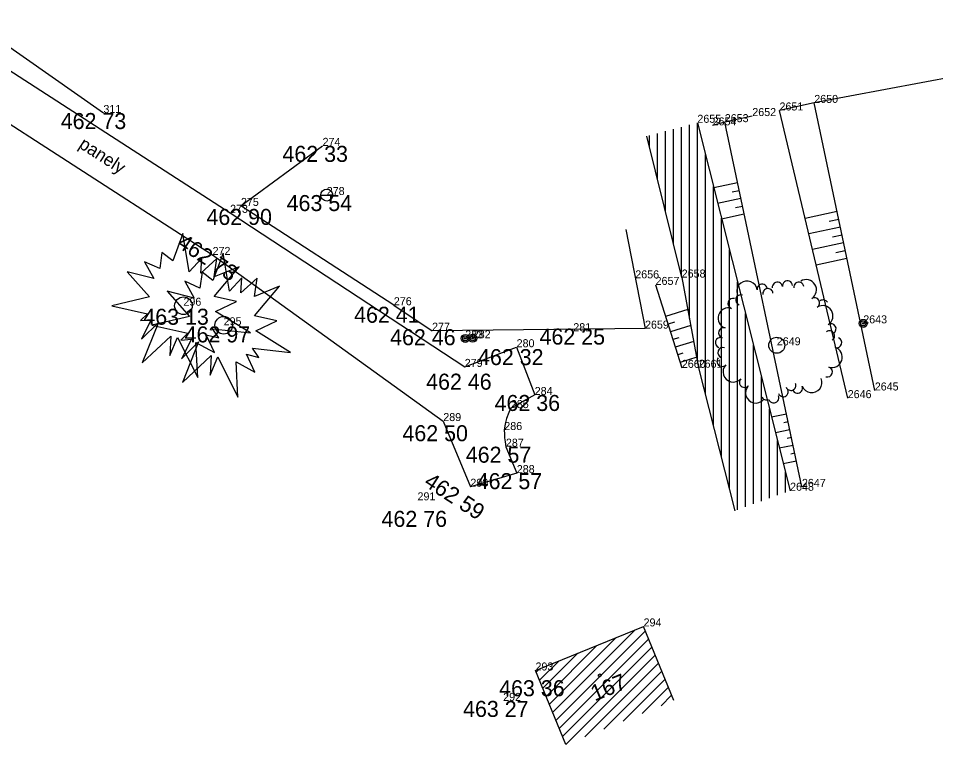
# Model space of a CAD drawing. Extents: x -559180 to -551373, y -1076947 to -1072071.
# Drawn here: x -553687 to -553629.7, y -1075512.9 to -1075467.6 of the extents above; entities that cross this region are included whole.
import ezdxf

# ---------------------------------------------------------------- set-up
doc = ezdxf.new("R2010")
doc.units = 0
for name, color, linetype in [('12_PLOTY', 7, 'Continuous'), ('14_BUDOVY', 7, 'Continuous'), ('17_KOMUNIKACE', 7, 'Continuous'), ('1_VODA_ZN', 7, 'Continuous'), ('20_EL_ZN', 7, 'Continuous'), ('26_SRAFY', 7, 'Continuous'), ('27_HRANA_PATA', 7, 'Continuous'), ('28_VODA', 7, 'Continuous'), ('32', 7, 'Continuous'), ('34_ZELEN', 7, 'Continuous'), ('3_BODY', 7, 'Continuous'), ('47_ZN_STAV_OBJ$', 7, 'Continuous'), ('52_POPIS_UCELOVY', 7, 'Continuous'), ('54_C_POPISNA', 7, 'Continuous'), ('6_VYSKY', 7, 'Continuous')]:
    doc.layers.add(name, color=color, linetype=linetype)

# ---------------------------------------------------------------- blocks, each defined once
blk = doc.blocks.new('POINT_DISPLAY')
blk.add_line((0, 0), (0, 0))
blk = doc.blocks.new('ST')
at = {"layer": '1_VODA_ZN'}
blk.add_line((-0.375, 0), (0.375, 0), dxfattribs=at)
blk.add_circle((0, 0), 0.375, dxfattribs=at)
blk = doc.blocks.new('SLDP')
at = {"layer": '20_EL_ZN'}
for radius in [0.25, 0.158, 0.05]:
    blk.add_circle((0, 0), radius, dxfattribs=at)
blk = doc.blocks.new('STJV')
at = {"layer": '34_ZELEN'}
blk.add_lwpolyline([(-4.477, 0), (-2.236, -0.499), (-2.682, -0.926), (-2.012, -0.869), (-2.627, -2.092), (-1.566, -1.04), (-2.57, -3.572), (-0.785, -1.893), (-0.841, -3.117), (-0.366, -1.979), (0.889, -4.483), (0.777, -2.291), (1.949, -2.917), (1.419, -1.808), (2.2, -2.006), (1.808, -1.437), (4.179, -1.694), (2.004, -0.356), (3.314, 0.27), (1.921, 0.582), (3.483, 2.432), (1.921, 1.806), (2.087, 2.944), (1.083, 2.034), (1.14, 2.972), (0.359, 2.119), (-0.033, 4.509), (-0.673, 2.802), (-1.343, 3.314), (-1.483, 2.318), (-2.431, 2.745), (-1.845, 1.692), (-3.519, 2.119), (-2.123, 0.554), (-4.477, 0)], dxfattribs=at)
blk.add_circle((0, 0), 0.55, dxfattribs=at)
blk = doc.blocks.new('BZ')
at = {"layer": '47_ZN_STAV_OBJ$'}
blk.add_circle((0, 0), 0.0875, dxfattribs=at)
blk = doc.blocks.new('STLV')
at = {"layer": '34_ZELEN'}
blk.add_circle((0, 0), 0.5, dxfattribs=at)
for centre, radius, start, end in [((-1.866, 3.377), 0.64, 7.279, 187.2791), ((0.673, 3.701), 0.32, 7.279, 187.2791), ((1.839, 3.46), 0.64, 302.4264, 122.4264), ((-0.914, 3.498), 0.32, 7.279, 187.2791), ((-0.552, 3.222), 0.32, 97.2791, 188.0812), ((-0.556, 3.222), 0.32, 6.4769, 97.2791), ((0.038, 3.62), 0.32, 7.279, 187.2791), ((1.372, 3.62), 0.32, 7.279, 187.2791), ((-2.733, 2.607), 0.32, 72.1317, 252.1317), ((-2.248, 2.834), 0.32, 72.1317, 252.1317), ((2.354, 2.649), 0.32, 302.4264, 122.4264), ((-3.027, 1.693), 0.64, 72.1317, 252.1317), ((2.869, 1.839), 0.64, 302.4264, 122.4264), ((2.893, 2.511), 0.32, 32.4264, 123.2285), ((3.383, 1.029), 0.32, 302.4264, 122.4264), ((-3.322, 0.779), 0.32, 72.1317, 252.1317), ((3.287, 0.583), 0.32, 32.4264, 123.2285), ((3.285, 0.587), 0.32, 301.6242, 32.4264), ((-3.518, 0.17), 0.32, 72.1317, 252.1317), ((3.746, 0.168), 0.32, 252.1317, 72.1317), ((-3.366, -0.453), 0.32, 72.1317, 252.1317), ((3.452, -0.746), 0.64, 252.1317, 72.1317), ((-3.419, -1.001), 0.32, 136.9844, 316.9844), ((-2.717, -1.656), 0.64, 136.9844, 316.9844), ((3.157, -1.66), 0.32, 252.1317, 72.1317), ((-2.015, -2.311), 0.32, 136.9844, 316.9844), ((2.185, -2.318), 0.64, 201.8371, 21.8371), ((-1.313, -2.966), 0.64, 136.9844, 316.9844), ((0.402, -2.891), 0.32, 201.8371, 21.8371), ((0.877, -2.497), 0.32, 201.035, 291.8371), ((0.873, -2.499), 0.32, 291.8371, 22.6393), ((1.293, -2.675), 0.32, 201.8371, 21.8371), ((-0.639, -3.093), 0.32, 201.035, 291.8371), ((-0.192, -3.27), 0.32, 201.8371, 21.8371)]:
    blk.add_arc(centre, radius, start, end, dxfattribs=at)
blk.add_blockref('POINT_DISPLAY', (0, 0), dxfattribs=at)

msp = doc.modelspace()

# ---------------------------------------------------------------- linework, layer by layer
at = {"layer": '12_PLOTY'}
for p, q in [((-553681.67, -1075473.52), (-553690.11, -1075467.61)), ((-553624.38, -1075470.48), (-553637.27, -1075472.89)), ((-553637.27, -1075472.89), (-553639.44, -1075473.36)), ((-553641.14, -1075473.71), (-553642.86, -1075474.09)), ((-553642.86, -1075474.09), (-553643.62, -1075474.29)), ((-553673.08, -1075479.32), (-553667.98, -1075475.57)), ((-553663.53, -1075485.52), (-553673.08, -1075479.32)), ((-553649.044, -1075480.781), (-553647.84, -1075486.98)), ((-553663.53, -1075485.52), (-553661.14, -1075487.11)), ((-553647.84, -1075486.98), (-553661.14, -1075487.11)), ((-553655.85, -1075496), (-553658.75, -1075496.85))]:
    msp.add_line(p, q, dxfattribs=at)
at = {"layer": '14_BUDOVY'}
for p, q in [((-553654.68, -1075508.32), (-553647.93, -1075505.57)), ((-553646.044, -1075510.2), (-553647.93, -1075505.57)), ((-553652.794, -1075512.95), (-553654.68, -1075508.32))]:
    msp.add_line(p, q, dxfattribs=at)
at = {"layer": '17_KOMUNIKACE'}
for p, q in [((-553691.57, -1075468.24), (-553673.76, -1075479.75)), ((-553692.78, -1075470.82), (-553674.85, -1075482.38)), ((-553673.76, -1075479.75), (-553659.1, -1075489.37)), ((-553674.85, -1075482.38), (-553660.44, -1075492.75)), ((-553659.1, -1075489.37), (-553655.86, -1075488.14)), ((-553655.86, -1075488.14), (-553654.73, -1075491.12)), ((-553654.73, -1075491.12), (-553656.22, -1075491.94)), ((-553660.44, -1075492.75), (-553658.75, -1075496.85)), ((-553656.53, -1075494.35), (-553655.85, -1075496))]:
    msp.add_line(p, q, dxfattribs=at)
for points in [[(-553656.22, -1075491.94), (-553656.354, -1075492.223), (-553656.488, -1075492.594), (-553656.571, -1075492.926), (-553656.63, -1075493.31)], [(-553656.63, -1075493.31), (-553656.627, -1075493.554), (-553656.609, -1075493.795), (-553656.579, -1075494.056), (-553656.53, -1075494.35)]]:
    msp.add_lwpolyline(points, dxfattribs=at)
at = {"layer": '26_SRAFY'}
for p, q in [((-553643.549, -1075478.179), (-553642.061, -1075477.864)), ((-553643.305, -1075479.15), (-553641.854, -1075478.843)), ((-553642.398, -1075478.447), (-553641.958, -1075478.353)), ((-553642.18, -1075479.423), (-553641.75, -1075479.332)), ((-553643.06, -1075480.12), (-553641.647, -1075479.821)), ((-553637.847, -1075480.076), (-553635.845, -1075479.655)), ((-553637.616, -1075481.049), (-553635.639, -1075480.633)), ((-553636.339, -1075480.27), (-553635.742, -1075480.144)), ((-553636.126, -1075481.247), (-553635.536, -1075481.122)), ((-553637.385, -1075482.023), (-553635.433, -1075481.612)), ((-553635.912, -1075482.224), (-553635.33, -1075482.101)), ((-553637.154, -1075482.996), (-553635.227, -1075482.59)), ((-553645.172, -1075485.795), (-553646.552, -1075486.232)), ((-553646.005, -1075486.583), (-553646.402, -1075486.709)), ((-553644.986, -1075486.785), (-553646.251, -1075487.186)), ((-553645.738, -1075487.548), (-553646.1, -1075487.662)), ((-553644.799, -1075487.775), (-553645.949, -1075488.139)), ((-553645.47, -1075488.512), (-553645.798, -1075488.616)), ((-553644.613, -1075488.765), (-553645.647, -1075489.092)), ((-553639.942, -1075492.49), (-553639.007, -1075492.292)), ((-553639.178, -1075492.839), (-553638.903, -1075492.781)), ((-553639.697, -1075493.46), (-553638.8, -1075493.27)), ((-553638.96, -1075493.815), (-553638.696, -1075493.759)), ((-553639.453, -1075494.431), (-553638.593, -1075494.249)), ((-553638.742, -1075494.791), (-553638.489, -1075494.738)), ((-553639.208, -1075495.401), (-553638.386, -1075495.227))]:
    msp.add_line(p, q, dxfattribs=at)
at = {"layer": '27_HRANA_PATA'}
for p, q in [((-553633.49, -1075490.84), (-553637.27, -1075472.89)), ((-553635.18, -1075491.32), (-553639.44, -1075473.36)), ((-553638.04, -1075496.86), (-553642.86, -1075474.09)), ((-553647.18, -1075484.25), (-553645.54, -1075489.43))]:
    msp.add_line(p, q, dxfattribs=at)
at = {"layer": '28_VODA'}
for p, q in [((-553644.57, -1075474.13), (-553638.78, -1075497.1)), ((-553645.55, -1075483.79), (-553647.722, -1075474.962)), ((-553645.55, -1075483.79), (-553644.49, -1075489.42)), ((-553644.49, -1075489.42), (-553642.231, -1075498.344))]:
    msp.add_line(p, q, dxfattribs=at)
at = {"layer": '32'}
for p, q in [((-553645.07, -1075486.339), (-553645.07, -1075474.262)), ((-553644.57, -1075488.995), (-553644.57, -1075474.13)), ((-553647.07, -1075477.612), (-553647.07, -1075474.79)), ((-553646.57, -1075479.644), (-553646.57, -1075474.658)), ((-553646.07, -1075481.676), (-553646.07, -1075474.526)), ((-553645.57, -1075483.709), (-553645.57, -1075474.394)), ((-553647.57, -1075475.58), (-553647.57, -1075474.922)), ((-553644.07, -1075491.079), (-553644.07, -1075476.114)), ((-553643.57, -1075493.054), (-553643.57, -1075478.097)), ((-553643.07, -1075495.03), (-553643.07, -1075480.081)), ((-553642.57, -1075497.005), (-553642.57, -1075482.064)), ((-553642.07, -1075498.286), (-553642.07, -1075484.048)), ((-553641.57, -1075498.106), (-553641.57, -1075486.032)), ((-553641.07, -1075497.925), (-553641.07, -1075488.015)), ((-553640.57, -1075497.745), (-553640.57, -1075489.999)), ((-553640.07, -1075497.565), (-553640.07, -1075491.982)), ((-553639.57, -1075497.385), (-553639.57, -1075493.966)), ((-553639.07, -1075497.205), (-553639.07, -1075495.95)), ((-553653.613, -1075510.94), (-553648.457, -1075505.785)), ((-553653.817, -1075510.438), (-553649.65, -1075506.271)), ((-553653.408, -1075511.443), (-553647.816, -1075505.85)), ((-553653.203, -1075511.945), (-553647.611, -1075506.353)), ((-553654.022, -1075509.935), (-553650.844, -1075506.757)), ((-553652.999, -1075512.448), (-553647.406, -1075506.855)), ((-553654.227, -1075509.433), (-553652.037, -1075507.243)), ((-553652.794, -1075512.95), (-553647.202, -1075507.358)), ((-553654.431, -1075508.93), (-553653.23, -1075507.729)), ((-553651.601, -1075512.464), (-553646.997, -1075507.86)), ((-553654.636, -1075508.428), (-553654.423, -1075508.215)), ((-553650.408, -1075511.978), (-553646.792, -1075508.363)), ((-553649.214, -1075511.492), (-553646.588, -1075508.865)), ((-553648.021, -1075511.005), (-553646.383, -1075509.368)), ((-553646.828, -1075510.519), (-553646.178, -1075509.87))]:
    msp.add_line(p, q, dxfattribs=at)

# ---------------------------------------------------------------- block references
at = {"layer": '1_VODA_ZN'}
for name, p in [('POINT_DISPLAY', (-553637.27, -1075472.89)), ('POINT_DISPLAY', (-553681.67, -1075473.52)), ('POINT_DISPLAY', (-553641.14, -1075473.71)), ('POINT_DISPLAY', (-553639.44, -1075473.36)), ('POINT_DISPLAY', (-553644.57, -1075474.13)), ('POINT_DISPLAY', (-553643.62, -1075474.29)), ('POINT_DISPLAY', (-553642.86, -1075474.09)), ('POINT_DISPLAY', (-553667.98, -1075475.57)), ('ST', (-553667.72, -1075478.64)), ('POINT_DISPLAY', (-553667.72, -1075478.64)), ('POINT_DISPLAY', (-553673.08, -1075479.32)), ('POINT_DISPLAY', (-553673.76, -1075479.75)), ('POINT_DISPLAY', (-553674.85, -1075482.38)), ('POINT_DISPLAY', (-553648.45, -1075483.84)), ('POINT_DISPLAY', (-553645.55, -1075483.79)), ('POINT_DISPLAY', (-553647.18, -1075484.25)), ('POINT_DISPLAY', (-553676.67, -1075485.55)), ('POINT_DISPLAY', (-553663.53, -1075485.52)), ('POINT_DISPLAY', (-553674.16, -1075486.77)), ('POINT_DISPLAY', (-553634.21, -1075486.65)), ('POINT_DISPLAY', (-553661.14, -1075487.11)), ('POINT_DISPLAY', (-553652.32, -1075487.14)), ('POINT_DISPLAY', (-553647.84, -1075486.98)), ('POINT_DISPLAY', (-553659.07, -1075487.59)), ('POINT_DISPLAY', (-553658.6, -1075487.58)), ('POINT_DISPLAY', (-553639.61, -1075488.02)), ('POINT_DISPLAY', (-553655.86, -1075488.14)), ('POINT_DISPLAY', (-553659.1, -1075489.37)), ('POINT_DISPLAY', (-553645.54, -1075489.43)), ('POINT_DISPLAY', (-553644.49, -1075489.42)), ('POINT_DISPLAY', (-553633.49, -1075490.84)), ('POINT_DISPLAY', (-553654.73, -1075491.12)), ('POINT_DISPLAY', (-553635.18, -1075491.32)), ('POINT_DISPLAY', (-553656.22, -1075491.94)), ('POINT_DISPLAY', (-553660.44, -1075492.75)), ('POINT_DISPLAY', (-553656.63, -1075493.31)), ('POINT_DISPLAY', (-553656.53, -1075494.35)), ('POINT_DISPLAY', (-553655.85, -1075496)), ('POINT_DISPLAY', (-553658.75, -1075496.85)), ('POINT_DISPLAY', (-553638.78, -1075497.1)), ('POINT_DISPLAY', (-553638.04, -1075496.86)), ('POINT_DISPLAY', (-553662.05, -1075497.7)), ('POINT_DISPLAY', (-553647.93, -1075505.57)), ('POINT_DISPLAY', (-553654.68, -1075508.32)), ('POINT_DISPLAY', (-553656.7, -1075510.22))]:
    msp.add_blockref(name, p, dxfattribs=at)
at = {"layer": '20_EL_ZN'}
for p in [(-553634.21, -1075486.65), (-553659.07, -1075487.59), (-553658.6, -1075487.58)]:
    msp.add_blockref('SLDP', p, dxfattribs=at)
at = {"layer": '32'}
msp.add_blockref('POINT_DISPLAY', (-553652.794, -1075512.95), dxfattribs=at)
at = {"layer": '34_ZELEN'}
for name, p in [('STJV', (-553676.67, -1075485.55)), ('STJV', (-553674.16, -1075486.77)), ('STLV', (-553639.61, -1075488.02))]:
    msp.add_blockref(name, p, dxfattribs=at)
at = {"layer": '47_ZN_STAV_OBJ$'}
msp.add_blockref('BZ', (-553650.669, -1075508.623), dxfattribs=at)

# ---------------------------------------------------------------- texts
at = {"layer": '3_BODY'}
for s, p in [('2650', (-553637.27, -1075472.89)), ('311', (-553681.67, -1075473.52)), ('2651', (-553639.44, -1075473.36)), ('2655', (-553644.57, -1075474.13)), ('2653', (-553642.86, -1075474.09)), ('2652', (-553641.14, -1075473.71)), ('2654', (-553643.62, -1075474.29)), ('274', (-553667.98, -1075475.57)), ('278', (-553667.72, -1075478.64)), ('275', (-553673.08, -1075479.32)), ('273', (-553673.76, -1075479.75)), ('272', (-553674.85, -1075482.38)), ('2656', (-553648.45, -1075483.84)), ('2658', (-553645.55, -1075483.79)), ('2657', (-553647.18, -1075484.25)), ('296', (-553676.67, -1075485.55)), ('276', (-553663.53, -1075485.52)), ('295', (-553674.16, -1075486.77)), ('2643', (-553634.21, -1075486.65)), ('277', (-553661.14, -1075487.11)), ('281', (-553652.32, -1075487.14)), ('2659', (-553647.84, -1075486.98)), ('283', (-553659.07, -1075487.59)), ('282', (-553658.6, -1075487.58)), ('280', (-553655.86, -1075488.14)), ('2649', (-553639.61, -1075488.02)), ('279', (-553659.1, -1075489.37)), ('2660', (-553645.54, -1075489.43)), ('2661', (-553644.49, -1075489.42)), ('2645', (-553633.49, -1075490.84)), ('284', (-553654.73, -1075491.12)), ('2646', (-553635.18, -1075491.32)), ('285', (-553656.22, -1075491.94)), ('289', (-553660.44, -1075492.75)), ('286', (-553656.63, -1075493.31)), ('287', (-553656.53, -1075494.35)), ('288', (-553655.85, -1075496)), ('290', (-553658.75, -1075496.85)), ('2648', (-553638.78, -1075497.1)), ('2647', (-553638.04, -1075496.86)), ('291', (-553662.05, -1075497.7)), ('294', (-553647.93, -1075505.57)), ('293', (-553654.68, -1075508.32)), ('292', (-553656.7, -1075510.22))]:
    msp.add_text(s, height=0.5, dxfattribs=at).set_placement(p)
at = {"layer": '52_POPIS_UCELOVY'}
msp.add_text('panely', height=0.8, rotation=327.1889, dxfattribs=at).set_placement((-553683.265, -1075475.646))
at = {"layer": '54_C_POPISNA'}
msp.add_text('167', height=1, rotation=22.1663, dxfattribs=at).set_placement((-553650.98, -1075510.255))
at = {"layer": '6_VYSKY'}
for s, p in [('462 73', (-553684.334, -1075474.52)), ('462 33', (-553670.485, -1075476.57)), ('463 54', (-553670.225, -1075479.64)), ('462 90', (-553675.233, -1075480.507)), ('463 13', (-553679.175, -1075486.737)), ('462 41', (-553666.011, -1075486.614)), ('462 97', (-553676.595, -1075487.84)), ('462 46', (-553663.762, -1075488.017)), ('462 25', (-553654.427, -1075487.976)), ('462 32', (-553658.271, -1075489.257)), ('462 46', (-553661.511, -1075490.791)), ('462 36', (-553657.235, -1075492.12)), ('462 50', (-553662.992, -1075494.008)), ('462 57', (-553659.035, -1075495.35)), ('462 57', (-553658.355, -1075497)), ('462 76', (-553664.298, -1075499.355)), ('463 36', (-553656.951, -1075509.929)), ('463 27', (-553659.205, -1075511.22))]:
    msp.add_text(s, height=1, dxfattribs=at).set_placement(p)
for s, rotation, p in [('462 73', 326.8194, (-553677.138, -1075481.838)), ('462 59', 326.9391, (-553661.715, -1075496.743))]:
    msp.add_text(s, height=1, rotation=rotation, dxfattribs=at).set_placement(p)

doc.saveas('drawing.dxf')
